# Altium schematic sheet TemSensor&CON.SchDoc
size A4; Revision: B.2
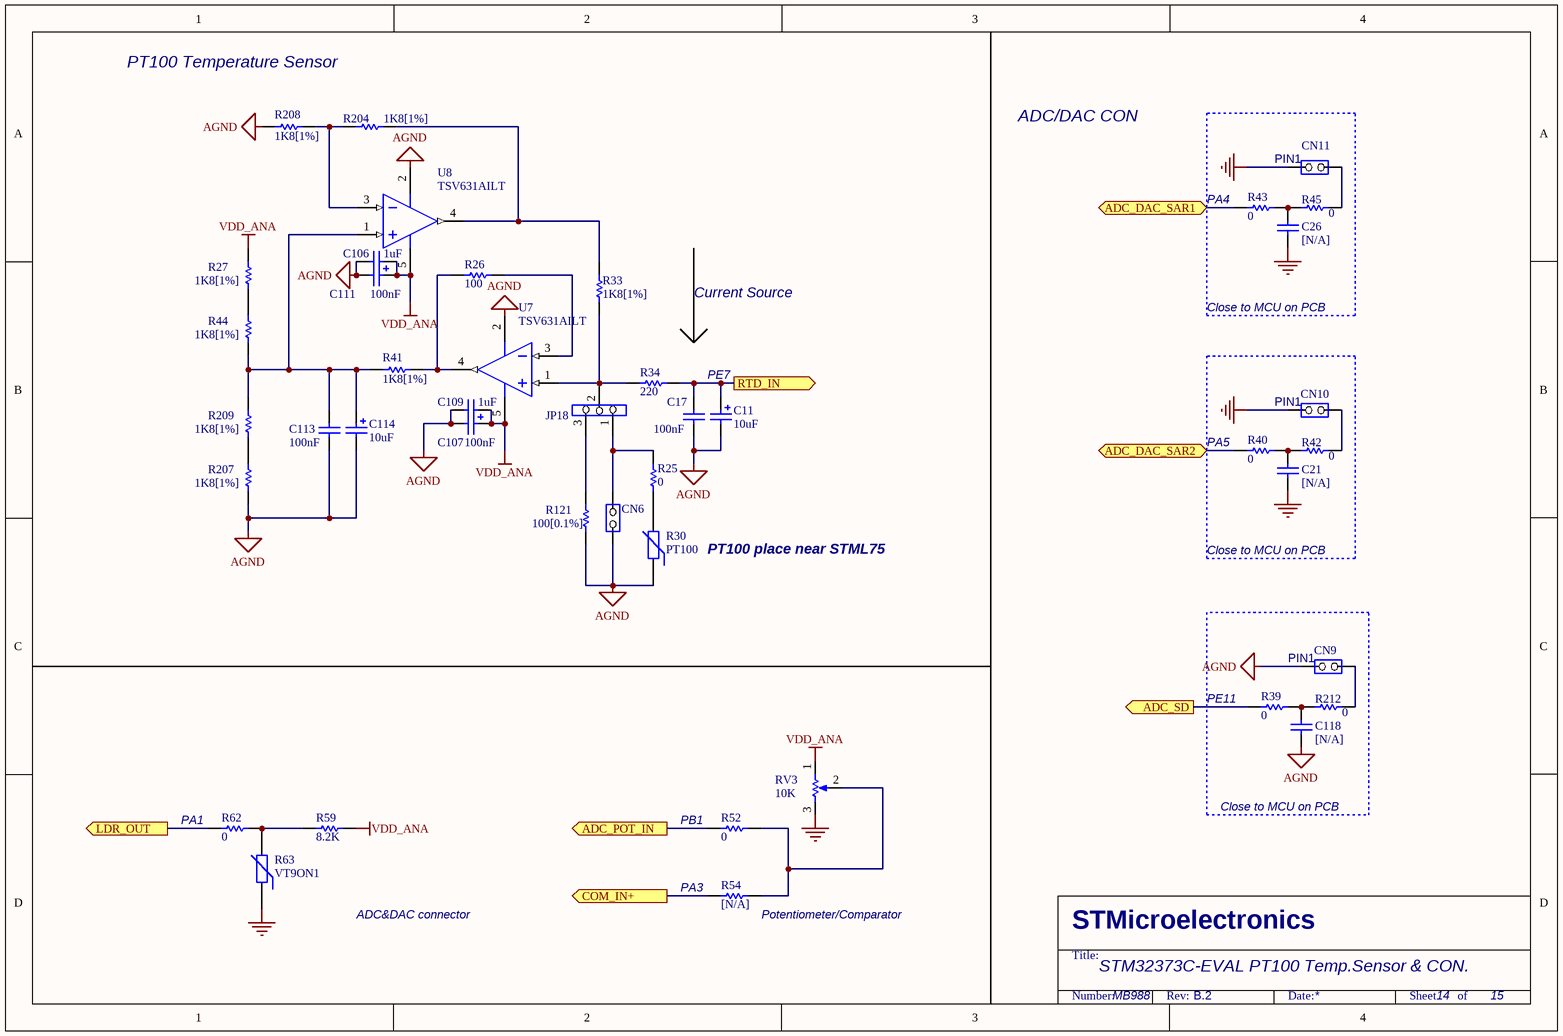
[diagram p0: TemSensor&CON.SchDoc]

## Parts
C11  10uF  [TAN-A]
C17  100nF  [0603C]
C21  [N/A]  [0603C]
C26  [N/A]  [0603C]
C106  1uF  [TAN-A]
C107  100nF  [0603C]
C109  1uF  [TAN-A]
C111  100nF  [0603C]
C113  100nF  [0603C]
C114  10uF  [TAN-A]
C118  [N/A]  [0603C]
CN6  (no value)  [SIP2]
CN9  (no value)  [SIP2]
CN10  (no value)  [SIP2]
CN11  (no value)  [SIP2]
JP18  (no value)  [SIP3]
R25  0  [0603R]
R26  100  [0603R]
R27  1K8[1%]  [0603R]
R30  PT100  [0805R]
R33  1K8[1%]  [0603R]
R34  220  [0603R]
R39  0  [0603R]
R40  0  [0603R]
R41  1K8[1%]  [0603R]
R42  0  [0603R]
R43  0  [0603R]
R44  1K8[1%]  [0603R]
R45  0  [0603R]
R52  0  [0603R]
R54  [N/A]  [0603R]
R59  8.2K  [0603R]
R62  0  [0603R]
R63  VT9ON1  [PVT901]
R121  100[0.1%]  [0603R]
R204  1K8[1%]  [0603R]
R207  1K8[1%]  [0603R]
R208  1K8[1%]  [0603R]
R209  1K8[1%]  [0603R]
R212  0  [0603R]
RV3  10K  [3296W]
U7  TSV631AILT  [SOT-23-5L]
U8  TSV631AILT  [SOT-23-5L]

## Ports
ADC_DAC_SAR1 (bidir), ADC_DAC_SAR2 (bidir), ADC_POT_IN (out), ADC_SD (out), COM_IN+ (out), LDR_OUT (out), RTD_IN (out)

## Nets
AGND: C11.2 C17.1 C106.2 C107.1 C109.2 C111.1 C113.1 C114.2 C118.1 CN6.2(NO) CN9.1(COMMON) R30.1 R121.2 R207.2 R208.1 U7.2(VDD) U8.2(VDD)
GND: C21.1 C26.1 CN10.1(COMMON) CN11.1(COMMON) R63.1 RV3.3(TOP)
VDD_ANA: C106.1 C107.2 C109.1 C111.2 R27.1 R59.2 RV3.1(BOT) U7.5(VCC) U8.5(VCC)
ADC_DAC_SAR1: R43.1 ; port ADC_DAC_SAR1
ADC_DAC_SAR2: R40.1 ; port ADC_DAC_SAR2
ADC_POT_IN: R52.1 ; port ADC_POT_IN
ADC_SD: R39.1 ; port ADC_SD
COM_IN+: R54.1 ; port COM_IN+
LDR_OUT: R62.2 ; port LDR_OUT
RTD_IN: C11.1 C17.2 R34.1 ; port RTD_IN
NetC21_2: C21.2 R40.2 R42.1
NetC26_2: C26.2 R43.2 R45.1
NetC113_2: C113.2 C114.1 R41.1 R44.2 R209.1 U8.1(IN+)
NetC118_2: C118.2 R39.2 R212.1
NetCN6_1: CN6.1(COMMON) JP18.1 R25.1
NetCN9_2: CN9.2(NO) R212.2
NetCN10_2: CN10.2(NO) R42.2
NetCN11_2: CN11.2(NO) R45.2
NetJP18_2: JP18.2 R33.2 R34.2 U7.1(IN+)
NetJP18_3: JP18.3 R121.1
NetR25_2: R25.2 R30.2
NetR26_1: R26.1 U7.3(IN-)
NetR26_2: R26.2 R41.2 U7.4(OUT)
NetR27_2: R27.2 R44.1
NetR33_1: R33.1 R204.2 U8.4(OUT)
NetR52_2: R52.2 R54.2 RV3.2(TAP)
NetR59_1: R59.1 R62.1 R63.2
NetR204_1: R204.1 R208.2 U8.3(IN-)
NetR207_1: R207.1 R209.2

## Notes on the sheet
- PT100 Temperature Sensor
- ADC/DAC CON
- (near CN11) PIN1
- (near R43) PA4
- Current Source
- Close to MCU on PCB
- PE7
- (near R40) PA5
- (near CN10) PIN1
- PT100 place near STML75
- (near R39) PE11
- (near CN9) PIN1
- (near R62) PA1
- (near R52) PB1
- ADC&DAC connector
- (near R54) PA3
- (near R54) Potentiometer/Comparator
- STM32373C-EVAL PT100 Temp.Sensor & CON.
- MB988
- 14
- 15

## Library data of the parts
C11 C114 = Cap Pol1: Polarized Capacitor (Radial)
C17 C107 C111 C113 = CAP: Capacitor; Value: 100pF
C21 C26 C118 = cap: Capacitor; Value: 100pF
C106 C109 = Cap Pol1: Polarized Capacitor (Radial); Value: 10uF
CN6 CN9-CN11 = JP2
JP18 = Jumper3
R25-R27 R33 R34 R39-R45 R52 R54 R59 R62 R121 R204 R207-R209 R212 = Res1: Resistor; Value: 1K
R30 = PT100: Varistor (Voltage-Sensitive Resistor)
R63 = Res Varistor: Varistor (Voltage-Sensitive Resistor)
RV3 = RV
